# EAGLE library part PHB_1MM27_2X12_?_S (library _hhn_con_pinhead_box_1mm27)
Pin Header Box-Type, 1.27mm/0.5"/50mil Pitch, 2x12 Circuits, single gates in schematic Note: see library description for an important note about THT-version
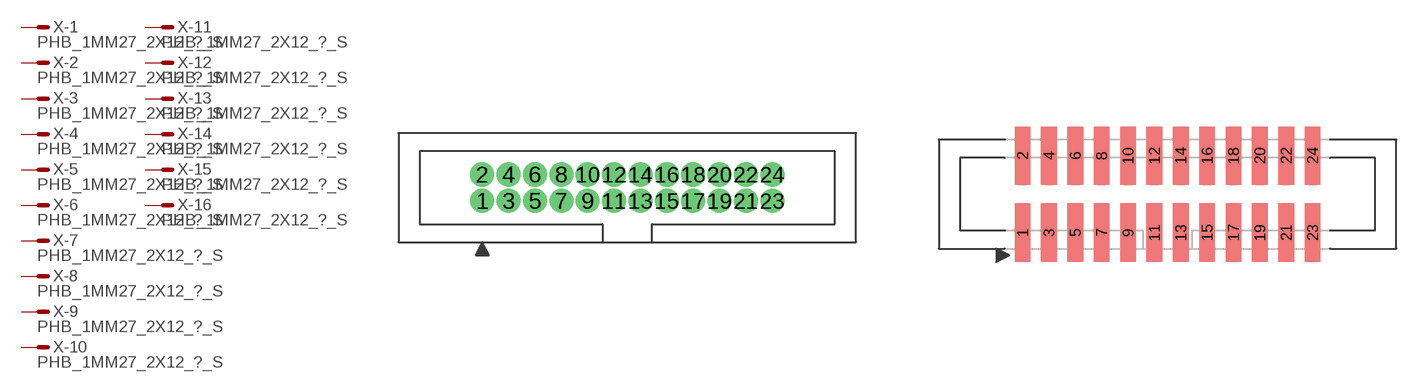
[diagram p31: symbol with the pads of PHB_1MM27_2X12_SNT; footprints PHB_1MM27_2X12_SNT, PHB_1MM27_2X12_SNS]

Designator prefix X; gates -1=M -2=M -3=M -4=M -5=M -6=M -7=M -8=M -9=M -10=M -11=M -12=M -13=M -14=M -15=M -16=M -17=M -18=M -19=M -20=M -21=M -22=M -23=M -24=M

## PHB_1MM27_2X12_SNT_S  [PHB_1MM27_2X12_SNT]
1  -1:S  pas
2  -2:S  pas
3  -3:S  pas
4  -4:S  pas
5  -5:S  pas
6  -6:S  pas
7  -7:S  pas
8  -8:S  pas
9  -9:S  pas
10  -10:S  pas
11  -11:S  pas
12  -12:S  pas
13  -13:S  pas
14  -14:S  pas
15  -15:S  pas
16  -16:S  pas
17  -17:S  pas
18  -18:S  pas
19  -19:S  pas
20  -20:S  pas
21  -21:S  pas
22  -22:S  pas
23  -23:S  pas
24  -24:S  pas

## PHB_1MM27_2X12_SNS_S  [PHB_1MM27_2X12_SNS]
Pads as for PHB_1MM27_2X12_SNT

## Footprint PHB_1MM27_2X12_SNT (pad centres in mm)
Pin Header Box-Type, 1.27mm Pitch, 2x12 circuits, Straight, No Locking, THT Important Note: Diameter in this lbr is set to a specific value (NOT 'auto' = 0), this is ignored by actual eagle versions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
drill 0.65 pad 1 round: 1 -6.985,-0.635; 2 -6.985,0.635; 3 -5.715,-0.635; 4 -5.715,0.635; 5 -4.445,-0.635; 6 -4.445,0.635; 7 -3.175,-0.635; 8 -3.175,0.635; 9 -1.905,-0.635; 10 -1.905,0.635; 11 -0.635,-0.635; 12 -0.635,0.635; 13 0.635,-0.635; 14 0.635,0.635; 15 1.905,-0.635; 16 1.905,0.635; 17 3.175,-0.635; 18 3.175,0.635; 19 4.445,-0.635; 20 4.445,0.635; 21 5.715,-0.635; 22 5.715,0.635; 23 6.985,-0.635; 24 6.985,0.635

## Footprint PHB_1MM27_2X12_SNS (pad centres in mm)
Pin Header Box-Type, 1.27mm Pitch, 2x12 circuits, Straight, No Locking, SMT
smd 0.76 x 2.8: 1 -6.985,-1.85; 2 -6.985,1.85; 3 -5.715,-1.85; 4 -5.715,1.85; 5 -4.445,-1.85; 6 -4.445,1.85; 7 -3.175,-1.85; 8 -3.175,1.85; 9 -1.905,-1.85; 10 -1.905,1.85; 11 -0.635,-1.85; 12 -0.635,1.85; 13 0.635,-1.85; 14 0.635,1.85; 15 1.905,-1.85; 16 1.905,1.85; 17 3.175,-1.85; 18 3.175,1.85; 19 4.445,-1.85; 20 4.445,1.85; 21 5.715,-1.85; 22 5.715,1.85; 23 6.985,-1.85; 24 6.985,1.85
